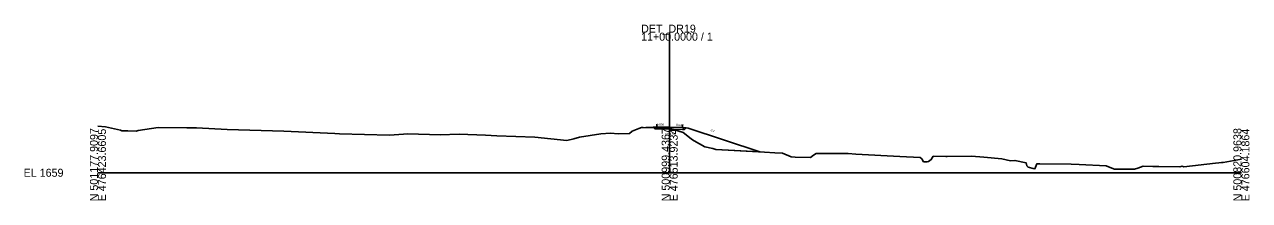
# Model space of a CAD drawing. Extents: x -26 to 403, y -10 to 3059.
# Drawn here: x -25.7 to 402.8, y 1490.3 to 1551.8 of the extents above; entities that cross this region are included whole.
import ezdxf

# ---------------------------------------------------------------- set-up
doc = ezdxf.new("R2010")
doc.units = 0
for name, color, linetype in [('Exist Cross Section Cell', 7, 'Continuous'), ('Exist XS Center Line Elevation Label', 7, 'Continuous'), ('Exist XS Ground Line', 7, 'Continuous'), ('Prop XS Dump Level', 7, 'Continuous'), ('Prop XS Earthwork Shape', 7, 'Continuous'), ('Prop XS EOT Tick Mark', 7, 'Continuous'), ('Prop XS Finish Grade', 7, 'Continuous'), ('Prop XS Finish Grade Earthwork', 7, 'Continuous'), ('Prop XS Finish Grade Pavement', 7, 'Continuous'), ('Prop XS Pvmt Edge Slope', 7, 'Continuous'), ('Prop XS SE Text', 7, 'Continuous'), ('Prop XS Shoulder Borrow Shape', 7, 'Continuous'), ('Prop XS Side Slope Text', 7, 'Continuous'), ('Prop XS Subgrade Earthwork', 7, 'Continuous')]:
    doc.layers.add(name, color=color, linetype=linetype)

msp = doc.modelspace()

# ---------------------------------------------------------------- linework, layer by layer
at = {"layer": 'Exist Cross Section Cell'}
for p, q in [((200, 1500), (200, 1548.97)), ((0, 1500), (200, 1500)), ((200, 1500), (400, 1500))]:
    msp.add_line(p, q, dxfattribs=at)
at = {"layer": 'Exist XS Ground Line'}
msp.add_lwpolyline([(0, 1516.32), (2.62, 1516.1), (7.88, 1514.89), (8.4, 1514.69), (10.49, 1514.61), (13.38, 1514.53), (14.07, 1514.76), (21.08, 1515.79), (31.08, 1515.66), (32.97, 1515.73), (34.43, 1515.67), (45.19, 1515.14), (64.98, 1514.5), (82.86, 1513.69), (84.48, 1513.62), (102.03, 1513.17), (106.85, 1513.51), (108.35, 1513.62), (119.67, 1513.22), (126.33, 1513.49), (135.56, 1513.11), (137.53, 1513.04), (139.56, 1512.96), (152.79, 1512.44), (164.02, 1511.32), (166.49, 1511.83), (168.46, 1512.41), (175.91, 1513.56), (179.3, 1513.85), (182.02, 1513.6), (185.9, 1513.75), (186.93, 1514.59), (189.23, 1515.52), (190.11, 1515.84), (190.7, 1515.85), (199.28, 1515.56), (200.24, 1515.51), (200.96, 1515.27), (204.78, 1514.08), (207.56, 1511.8), (207.98, 1511.49), (208.57, 1511.19), (212.29, 1509.07), (215.11, 1508.48), (216.18, 1508.09), (233.17, 1507.19), (236.74, 1506.92), (239.43, 1506.82), (242.54, 1505.56), (243.92, 1505.43), (249.23, 1505.31), (250.37, 1506.11), (251.23, 1506.76), (262.49, 1506.76), (265.13, 1506.49), (280.49, 1505.72), (287.58, 1505.35), (288.17, 1504.85), (288.8, 1503.83), (290.03, 1503.85), (290.6, 1503.88), (291.48, 1504.62), (292.22, 1505.77), (296.57, 1505.71), (297.13, 1505.69), (305.54, 1505.77), (309.95, 1505.45), (316.16, 1504.84), (319.23, 1504.19), (320.77, 1504.29), (324.71, 1503.51), (324.98, 1502.38), (325.44, 1501.97), (327.21, 1501.49), (327.79, 1501.39), (328.42, 1503.06), (329.44, 1503.12), (340.43, 1502.95), (343.27, 1502.9), (352.71, 1502.44), (354.08, 1501.89), (355.64, 1501.29), (356.25, 1501.27), (362.64, 1501.31), (363.74, 1501.62), (365.69, 1502.35), (369.04, 1502.19), (371.17, 1502.15), (378.52, 1502.05), (379.34, 1502.27), (379.88, 1502.06), (390.94, 1503.34), (392.17, 1503.47), (393.09, 1503.56), (393.62, 1503.62), (400, 1504.78)], dxfattribs=at)
at = {"layer": 'Prop XS Dump Level'}
for p, q in [((195.5, 1515.97), (200, 1515.88)), ((200, 1515.88), (204.5, 1515.79))]:
    msp.add_line(p, q, dxfattribs=at)
at = {"layer": 'Prop XS Earthwork Shape'}
for points in [[(194.24, 1515.92), (191.68, 1515.82), (194.44, 1515.72)], [(199.28, 1515.56), (200.24, 1515.51), (200.96, 1515.27), (201.2, 1515.19), (200, 1515.22), (195.5, 1515.31), (194.85, 1515.32), (194.44, 1515.72)], [(204.5, 1515.13), (205.18, 1515.11), (205.76, 1515.69), (206.5, 1515.63), (231.6, 1507.27), (216.18, 1508.09), (215.11, 1508.48), (212.29, 1509.07), (208.57, 1511.19), (207.98, 1511.49), (207.56, 1511.8), (204.78, 1514.08), (201.2, 1515.19)]]:
    msp.add_lwpolyline(points, close=True, dxfattribs=at)
at = {"layer": 'Prop XS EOT Tick Mark'}
for p, q in [((195.5, 1515.97), (195.5, 1516.97)), ((204.5, 1515.79), (204.5, 1516.79))]:
    msp.add_line(p, q, dxfattribs=at)
at = {"layer": 'Prop XS Finish Grade'}
for p, q in [((195.5, 1515.97), (194.24, 1515.92)), ((204.5, 1515.79), (205.76, 1515.69))]:
    msp.add_line(p, q, dxfattribs=at)
at = {"layer": 'Prop XS Finish Grade Earthwork'}
for p, q in [((194.24, 1515.92), (191.68, 1515.82)), ((205.76, 1515.69), (206.5, 1515.63)), ((206.5, 1515.63), (231.6, 1507.27))]:
    msp.add_line(p, q, dxfattribs=at)
at = {"layer": 'Prop XS Finish Grade Pavement'}
for p, q in [((195.5, 1515.97), (200, 1515.88)), ((200, 1515.88), (204.5, 1515.79))]:
    msp.add_line(p, q, dxfattribs=at)
at = {"layer": 'Prop XS Pvmt Edge Slope'}
for p, q in [((195.5, 1515.97), (194.85, 1515.32)), ((204.5, 1515.79), (205.18, 1515.11))]:
    msp.add_line(p, q, dxfattribs=at)
at = {"layer": 'Prop XS Shoulder Borrow Shape'}
for points in [[(195.5, 1515.97), (194.24, 1515.92), (194.85, 1515.32)], [(204.5, 1515.79), (205.76, 1515.69), (205.18, 1515.11)]]:
    msp.add_lwpolyline(points, close=True, dxfattribs=at)
at = {"layer": 'Prop XS Subgrade Earthwork'}
for p, q in [((194.85, 1515.32), (194.24, 1515.92)), ((195.5, 1515.31), (194.85, 1515.32)), ((200, 1515.22), (195.5, 1515.31)), ((204.5, 1515.13), (200, 1515.22)), ((204.5, 1515.13), (205.18, 1515.11)), ((205.18, 1515.11), (205.76, 1515.69))]:
    msp.add_line(p, q, dxfattribs=at)

# ---------------------------------------------------------------- texts
at = {"layer": 'Exist Cross Section Cell'}
for s, p in [('DET_DR19', (190, 1548.97)), ('11+00.0000 / 1', (190, 1546.17)), ('EL 1659', (-26, 1498.6))]:
    msp.add_text(s, height=2.8, dxfattribs=at).set_placement(p)
for s, p in [('N 501177.9097', (0, 1490)), ('E 476423.6605', (2.8, 1490)), ('N 500999.4367', (200, 1490)), ('E 476513.9234', (202.8, 1490)), ('N 500820.9638', (400, 1490)), ('E 476604.1864', (402.8, 1490))]:
    msp.add_text(s, height=2.8, rotation=90, dxfattribs=at).set_placement(p)
at = {"layer": 'Exist XS Center Line Elevation Label'}
msp.add_text('1674.52', height=0.75, dxfattribs=at).set_placement((198.26, 1513.14))
at = {"layer": 'Prop XS Dump Level'}
for p in [(193.5, 1515.85), (206.5, 1515.59)]:
    msp.add_text('Case1', height=0.04, dxfattribs=at).set_placement(p)
at = {"layer": 'Prop XS SE Text'}
for p in [(195.46, 1516.45), (202.27, 1516.36)]:
    msp.add_text('0.020', height=0.75, rotation=358.8542, dxfattribs=at).set_placement(p)
at = {"layer": 'Prop XS Side Slope Text'}
msp.add_text('3:1', height=0.75, rotation=341.5798, dxfattribs=at).set_placement((214.29, 1514.62))

doc.saveas('drawing.dxf')
